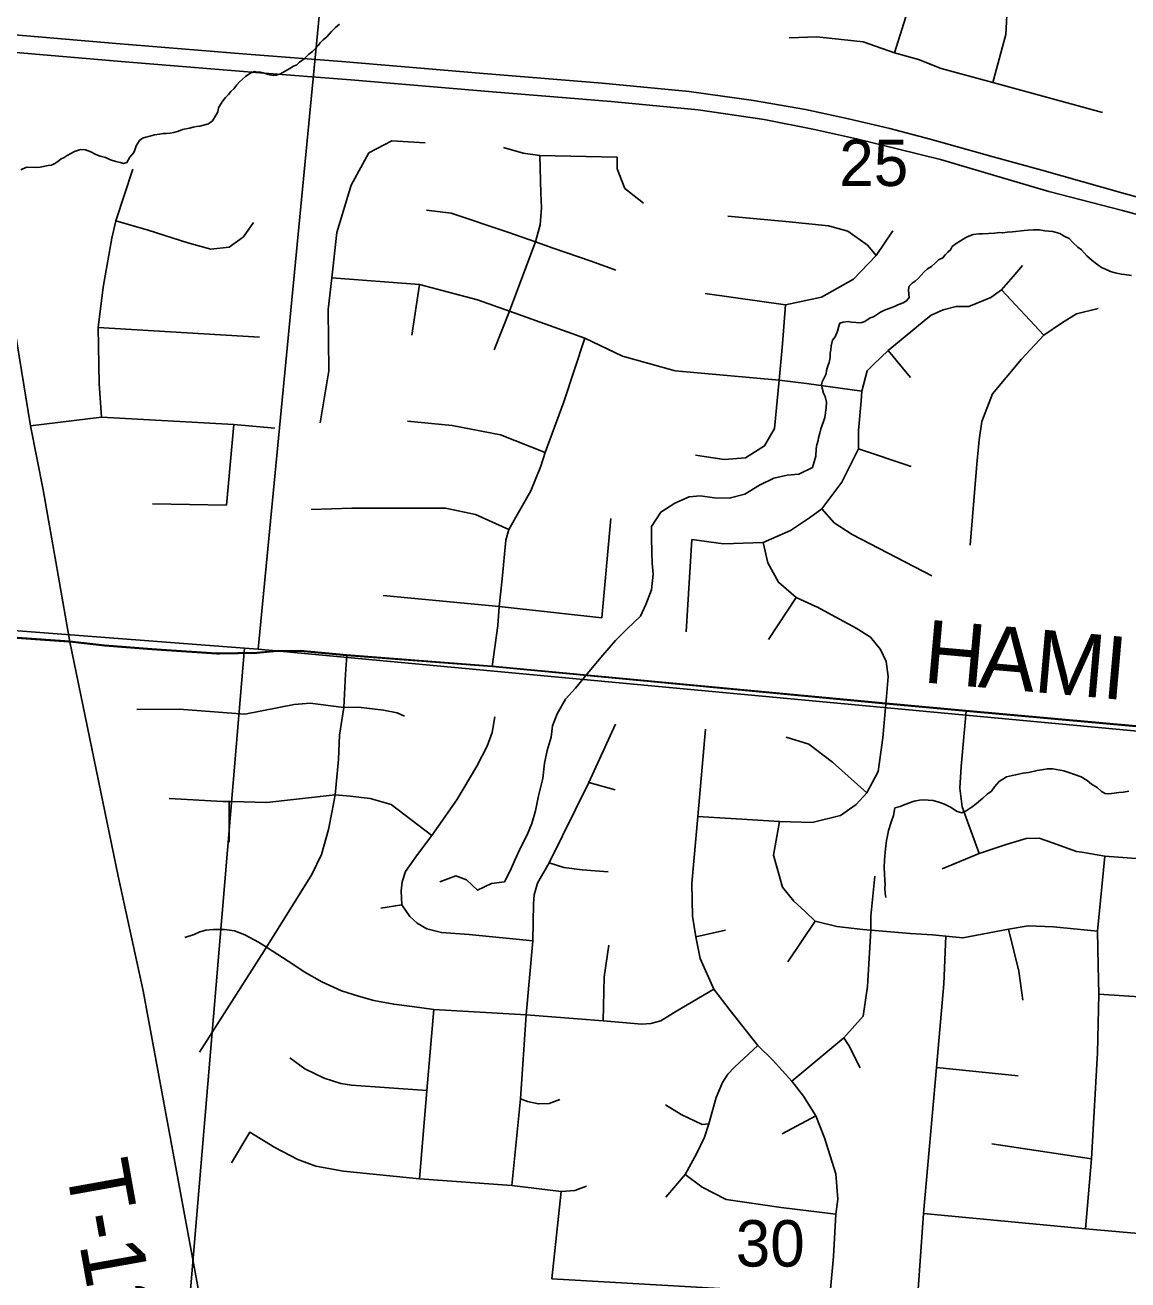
# Model space of a CAD drawing. Extents: x 0 to 34, y 0 to 22.
# Drawn here: x 6.638 to 7.633, y 19.591 to 20.723 of the extents above; entities that cross this region are included whole.
import ezdxf

# ---------------------------------------------------------------- set-up
doc = ezdxf.new("R2010")
doc.units = 0
for name, color, linetype in [('Default', 7, 'Continuous'), ('GM_X_Minor_River', 7, 'Continuous'), ('GM_X_Section', 7, 'Continuous'), ('GM_X_Section_Text', 7, 'Continuous'), ('GM_X_State_Route', 7, 'Continuous'), ('GM_X_Township_Road', 7, 'Continuous'), ('GM_X_Township_Road_Text', 7, 'Continuous')]:
    doc.layers.add(name, color=color, linetype=linetype)

msp = doc.modelspace()

# ---------------------------------------------------------------- linework, layer by layer
at = {"layer": 'Default'}
for points in [[(6.92, 20.9), (5.8864, 20.9), (5.8307, 20.238), (6.8362, 20.1611), (6.8487, 20.1601)], [(7.9386, 20.9), (6.92, 20.9), (6.8487, 20.1601), (7.855, 20.0664)]]:
    msp.add_lwpolyline(points, close=True, dxfattribs=at)
at = {"layer": 'GM_X_Minor_River'}
for points in [[(6.9221, 20.7242), (6.9183, 20.7212), (6.9148, 20.7175), (6.9105, 20.7126), (6.9074, 20.71), (6.9047, 20.7074), (6.9028, 20.7048), (6.9004, 20.7022), (6.8977, 20.6996), (6.8943, 20.697), (6.89, 20.6929), (6.8858, 20.6899), (6.8834, 20.6873), (6.8804, 20.6863), (6.8765, 20.6837), (6.8688, 20.6793), (6.865, 20.6782), (6.8624, 20.6779), (6.8593, 20.6783), (6.8533, 20.6803), (6.8506, 20.6808), (6.848, 20.6808), (6.8453, 20.6813), (6.8419, 20.6802), (6.8373, 20.6769), (6.8319, 20.672), (6.8295, 20.6694), (6.8268, 20.6657), (6.8241, 20.6635), (6.8218, 20.6608), (6.8191, 20.6579), (6.8167, 20.6549), (6.8148, 20.6515), (6.8128, 20.6485), (6.8124, 20.6451), (6.8108, 20.6424), (6.8073, 20.6368), (6.8038, 20.6342), (6.7961, 20.6321), (6.7931, 20.6318), (6.7901, 20.6311), (6.7866, 20.6304), (6.7805, 20.629), (6.7767, 20.6276), (6.7725, 20.6265), (6.7694, 20.6258), (6.766, 20.6255), (6.763, 20.6256), (6.7596, 20.6249), (6.755, 20.6242), (6.7508, 20.6231), (6.7473, 20.6221), (6.7443, 20.6214), (6.7416, 20.6191), (6.7385, 20.6143), (6.7376, 20.6112), (6.7364, 20.6082), (6.7329, 20.6041), (6.7302, 20.5992), (6.7271, 20.5985), (6.7241, 20.5994), (6.7203, 20.6002), (6.7154, 20.6018), (6.7109, 20.6038), (6.706, 20.605), (6.7022, 20.6066), (6.6977, 20.609), (6.6928, 20.6106), (6.6883, 20.6111), (6.6829, 20.6093), (6.6764, 20.6056), (6.6737, 20.6038), (6.671, 20.6027), (6.6679, 20.6001), (6.6652, 20.5983), (6.6622, 20.5968), (6.6591, 20.5965)], [(6.6591, 20.5965), (6.6519, 20.5951), (6.6485, 20.5948), (6.6397, 20.595), (6.6344, 20.5928)], [(7.6366, 20.4973), (7.6301, 20.4982), (7.6275, 20.4986), (7.6218, 20.4999), (7.6177, 20.5011), (7.6131, 20.5031), (7.6101, 20.5043), (7.6075, 20.5062), (7.6049, 20.5078), (7.6011, 20.5109), (7.5963, 20.5152), (7.5915, 20.5206), (7.5881, 20.523), (7.584, 20.5269), (7.5803, 20.5307), (7.5757, 20.5327), (7.572, 20.5351), (7.5656, 20.5371), (7.5584, 20.5376), (7.5535, 20.5385), (7.5481, 20.5386), (7.5432, 20.5383), (7.5398, 20.538), (7.5291, 20.5367), (7.5245, 20.5364), (7.5204, 20.5357), (7.5177, 20.5362), (7.5128, 20.5355), (7.5021, 20.535), (7.4987, 20.535), (7.4937, 20.5344), (7.4899, 20.5329), (7.4872, 20.5315), (7.4822, 20.5285), (7.4784, 20.5263), (7.4749, 20.5234), (7.4733, 20.5204), (7.4707, 20.5185), (7.4683, 20.5159), (7.4664, 20.5133), (7.4625, 20.5115), (7.4598, 20.5089), (7.456, 20.5055), (7.4525, 20.5033), (7.4494, 20.5007), (7.4467, 20.4977), (7.444, 20.4947), (7.4413, 20.4921), (7.4386, 20.4903), (7.4359, 20.4877), (7.4354, 20.4846), (7.4357, 20.4801), (7.436, 20.4774), (7.4337, 20.4744), (7.4306, 20.4726), (7.4257, 20.4708), (7.4226, 20.4693), (7.4195, 20.4682), (7.4138, 20.4661), (7.41, 20.4643), (7.4073, 20.4624), (7.4038, 20.4602), (7.4008, 20.4591), (7.3961, 20.4558), (7.3923, 20.4547), (7.384, 20.4553), (7.3809, 20.4557), (7.3764, 20.4551), (7.3733, 20.4544), (7.3725, 20.4517), (7.3713, 20.4472), (7.3693, 20.4419), (7.3669, 20.4389), (7.3657, 20.434)], [(7.3657, 20.434), (7.3652, 20.4302), (7.3648, 20.4272), (7.3647, 20.4234), (7.3639, 20.4188), (7.3627, 20.4158), (7.3615, 20.4117), (7.361, 20.4086), (7.3595, 20.4056), (7.3575, 20.4015), (7.357, 20.3988), (7.3574, 20.3958), (7.3588, 20.3912), (7.3602, 20.3881), (7.3613, 20.3832), (7.3612, 20.3779), (7.3599, 20.3691), (7.3587, 20.3657), (7.3563, 20.359), (7.3554, 20.3552), (7.3542, 20.351), (7.3538, 20.3484), (7.3526, 20.3446), (7.3521, 20.3412)], [(7.3521, 20.3412), (7.3517, 20.3343), (7.3488, 20.3242), (7.3365, 20.318), (7.3259, 20.3171), (7.314, 20.3144), (7.3009, 20.3083), (7.2878, 20.2999), (7.2737, 20.2964), (7.2604, 20.2968), (7.2475, 20.2986), (7.2376, 20.2977), (7.2246, 20.292), (7.2118, 20.2839), (7.2035, 20.2708), (7.2036, 20.2606), (7.2037, 20.2476), (7.2042, 20.2377), (7.2051, 20.2278), (7.2036, 20.2138), (7.1983, 20.2006), (7.1935, 20.1901), (7.1814, 20.1786), (7.1709, 20.1679), (7.1596, 20.1549), (7.1486, 20.1415), (7.1349, 20.1251), (7.1259, 20.1151), (7.1184, 20.1019), (7.1143, 20.091), (7.1129, 20.0808), (7.1095, 20.0687), (7.107, 20.0574), (7.1055, 20.0434), (7.1017, 20.0279), (7.0987, 20.0143), (7.0954, 20.0029), (7.0913, 19.9928), (7.0853, 19.9808), (7.0801, 19.9699), (7.076, 19.9601), (7.0709, 19.9503), (7.059, 19.9487), (7.0464, 19.9426), (7.0367, 19.952), (7.0269, 19.9556), (7.0124, 19.9503)], [(7.6341, 20.0322), (7.6292, 20.0312), (7.625, 20.0309), (7.6208, 20.0303), (7.6162, 20.0297), (7.6128, 20.0298), (7.6094, 20.0318), (7.6057, 20.0353), (7.6005, 20.0385), (7.5964, 20.0417), (7.5912, 20.0449), (7.5799, 20.049), (7.5754, 20.0503), (7.5655, 20.0521), (7.5606, 20.0523), (7.5572, 20.0516), (7.5514, 20.0507), (7.5438, 20.049), (7.5388, 20.0484), (7.5319, 20.0467), (7.5239, 20.045), (7.5173, 20.0407), (7.513, 20.0359), (7.5102, 20.0322), (7.5063, 20.0292), (7.5024, 20.0256), (7.4966, 20.0208), (7.4927, 20.0179), (7.4873, 20.0142), (7.4834, 20.0125), (7.4793, 20.0137), (7.4733, 20.0177), (7.4677, 20.0202)], [(7.4677, 20.0202), (7.4628, 20.0222), (7.4575, 20.0235), (7.453, 20.024), (7.4495, 20.0241), (7.4454, 20.0239), (7.4404, 20.0229), (7.4346, 20.0208), (7.4277, 20.0183), (7.4231, 20.017), (7.4218, 20.0102), (7.4197, 20.0041), (7.4172, 19.9966), (7.4163, 19.9917), (7.4154, 19.9875), (7.4149, 19.9826), (7.4143, 19.9769), (7.4137, 19.9697), (7.4135, 19.9633), (7.4138, 19.9576), (7.414, 19.9515), (7.4142, 19.948), (7.4141, 19.9446), (7.4144, 19.9397), (7.415, 19.9362)]]:
    msp.add_lwpolyline(points, dxfattribs=at)
at = {"layer": 'GM_X_Section'}
for points in [[(5.8307, 20.238), (6.8362, 20.1611), (6.7522, 19.1603), (5.7435, 19.3869), (5.8084, 20.2412)], [(6.8362, 20.1611), (6.8487, 20.1601), (7.855, 20.0664), (7.8637, 20.0659), (7.7938, 19.1583), (6.7522, 19.1603)]]:
    msp.add_lwpolyline(points, close=True, dxfattribs=at)
at = {"layer": 'GM_X_State_Route'}
for points in [[(6.5479, 20.7215), (6.7205, 20.7068), (6.8383, 20.6971), (6.924, 20.6905), (7.0518, 20.6797), (7.1589, 20.671), (7.2374, 20.6633), (7.2954, 20.6552), (7.3424, 20.6471), (7.3813, 20.6386), (7.4186, 20.63), (7.4549, 20.6203), (7.5117, 20.6045), (7.5555, 20.5923), (7.6278, 20.5719), (7.6871, 20.5558)], [(6.5561, 20.7048), (6.7287, 20.6902), (6.8465, 20.6805), (6.9322, 20.6739), (7.06, 20.6631), (7.1671, 20.6543), (7.2456, 20.6467), (7.3051, 20.6381), (7.3505, 20.629), (7.3885, 20.6208), (7.4642, 20.6019), (7.5203, 20.5856), (7.5619, 20.5732), (7.6283, 20.5559)], [(7.6283, 20.5559), (7.6361, 20.5538), (7.6945, 20.538), (7.7505, 20.5224), (7.8012, 20.5086), (7.8343, 20.4986), (7.8682, 20.4894)]]:
    msp.add_lwpolyline(points, dxfattribs=at)
at = {"layer": 'GM_X_Township_Road'}
for p, q in [((6.9943, 20.4891), (6.9873, 20.4436)), ((7.5574, 20.4434), (7.5192, 20.4844)), ((6.7044, 20.4503), (6.8499, 20.4416)), ((7.4171, 20.4297), (7.4373, 20.4053)), ((7.3902, 20.3408), (7.4379, 20.325)), ((7.3091, 20.1689), (7.334, 20.2069)), ((7.1469, 20.0398), (7.1707, 20.0333)), ((6.8224, 19.986), (6.8224, 20.0227)), ((6.9594, 19.9266), (6.9783, 19.9295)), ((7.2436, 19.9006), (7.2703, 19.9067)), ((7.3512, 19.9149), (7.3264, 19.8781)), ((7.4607, 19.7828), (7.5343, 19.7753)), ((7.3519, 19.7392), (7.3214, 19.7228)), ((7.6006, 19.7003), (7.5104, 19.7138)), ((7.1137, 19.5921), (7.1219, 19.6708)), ((7.1137, 19.5921), (7.265, 19.5834))]:
    msp.add_line(p, q, dxfattribs=at)
for points in [[(6.4945, 20.1803), (6.6784, 20.1674), (6.71, 20.1637), (6.7526, 20.1604), (6.7658, 20.1595), (6.8112, 20.1567), (6.8137, 20.1565), (6.8473, 20.1572), (6.8656, 20.1588), (6.8864, 20.1589), (6.9284, 20.155), (7.0596, 20.1449), (7.4148, 20.1115), (7.4871, 20.1047), (7.7604, 20.0801), (7.7765, 20.0797), (7.8238, 20.073), (7.9584, 20.0596), (8.6673, 19.9886), (8.7085, 19.9845), (8.8165, 19.9737), (8.9, 19.9667), (8.9, 20.9), (3.8479, 20.9)], [(7.4227, 20.6983), (7.4415, 20.7578), (7.4485, 20.7764), (7.4538, 20.7877), (7.4598, 20.8021), (7.4635, 20.8167), (7.4641, 20.8314)], [(7.5114, 20.6715), (7.5231, 20.7148), (7.5248, 20.7438), (7.5587, 20.7528)], [(7.3276, 20.7118), (7.3527, 20.7128), (7.3945, 20.7081), (7.4227, 20.6983), (7.4445, 20.6921), (7.4648, 20.6841), (7.5114, 20.6715), (7.6104, 20.6445)], [(6.6786, 20.1669), (6.6661, 20.2389), (6.6547, 20.3041), (6.6433, 20.3617), (6.6228, 20.4875), (6.6064, 20.5918), (6.5991, 20.6144), (6.591, 20.632)], [(6.9045, 20.3644), (6.9124, 20.4114), (6.9119, 20.4667), (6.9152, 20.4953), (6.9195, 20.536), (6.9326, 20.5789), (6.9486, 20.608), (6.9693, 20.6188), (6.9994, 20.6172)], [(7.0701, 20.6129), (7.0876, 20.6076), (7.1028, 20.6057), (7.1725, 20.6041), (7.1725, 20.5936), (7.1793, 20.5759), (7.1964, 20.5625)], [(7.0615, 20.4303), (7.0753, 20.4652), (7.0884, 20.4997), (7.0988, 20.5276), (7.1031, 20.5432), (7.1044, 20.5583), (7.1038, 20.5717), (7.1028, 20.6057)], [(6.7074, 20.3695), (6.7052, 20.3998), (6.7044, 20.4503), (6.7089, 20.4867), (6.7165, 20.5309), (6.7202, 20.5468), (6.7355, 20.5934)], [(7.0005, 20.5562), (7.0229, 20.5537), (7.074, 20.5364), (7.0988, 20.5276), (7.1147, 20.5219), (7.1492, 20.5103), (7.1713, 20.5023)], [(7.2723, 20.551), (7.3247, 20.5462), (7.3632, 20.5421), (7.3807, 20.5372), (7.3984, 20.5247), (7.4062, 20.5154)], [(6.7202, 20.5468), (6.7493, 20.5382), (6.7852, 20.5268), (6.8059, 20.5211), (6.8224, 20.5228), (6.8354, 20.5321), (6.8443, 20.5452)], [(7.252, 20.4811), (7.3245, 20.4709), (7.3569, 20.4779), (7.3858, 20.494), (7.4062, 20.5154), (7.4211, 20.5377)], [(7.2349, 20.1759), (7.2399, 20.259), (7.2686, 20.2552), (7.3043, 20.2563), (7.3288, 20.2672), (7.3461, 20.2788), (7.3572, 20.2869), (7.3751, 20.3108), (7.3902, 20.3408), (7.3902, 20.3574), (7.3927, 20.3843), (7.3932, 20.3929), (7.398, 20.4113), (7.4037, 20.4169), (7.4171, 20.4297), (7.4496, 20.4564), (7.4558, 20.4616), (7.4665, 20.4664), (7.4785, 20.4693), (7.4897, 20.4693), (7.5097, 20.4774), (7.5192, 20.4844), (7.5297, 20.4963), (7.5381, 20.5065)], [(6.9152, 20.4953), (6.9943, 20.4891), (7.0466, 20.4754), (7.0753, 20.4652), (7.1434, 20.4408), (7.1774, 20.4247), (7.2248, 20.4113), (7.3186, 20.4029), (7.3434, 20.4), (7.3932, 20.3929)], [(7.2433, 20.3353), (7.269, 20.3312), (7.2883, 20.3327), (7.3055, 20.3436), (7.3145, 20.3594), (7.3186, 20.4029), (7.3218, 20.4356), (7.3245, 20.4709)], [(7.4911, 20.2541), (7.4971, 20.327), (7.4992, 20.3491), (7.5016, 20.3656), (7.5111, 20.3905), (7.5374, 20.422), (7.5574, 20.4434), (7.5735, 20.4543), (7.5868, 20.4627), (7.6064, 20.4676)], [(7.0599, 20.1444), (7.0649, 20.1815), (7.066, 20.1986), (7.0689, 20.2237), (7.072, 20.2586), (7.0748, 20.2682), (7.0947, 20.3031), (7.1037, 20.3252), (7.1076, 20.3376), (7.1244, 20.3833), (7.1434, 20.4408)], [(6.6433, 20.3617), (6.7074, 20.3695), (6.8267, 20.3628), (6.8636, 20.3595)], [(6.7532, 20.2913), (6.82, 20.2902), (6.8267, 20.3628)], [(7.1076, 20.3376), (7.0672, 20.3537), (7.0236, 20.362), (6.9833, 20.3659)], [(5.1625, 20.2909), (5.3045, 20.2803), (5.4879, 20.2628), (5.632, 20.2501), (5.6711, 20.2466), (5.8283, 20.2358), (5.9419, 20.2248), (5.9874, 20.2213), (6.1326, 20.2085), (6.1948, 20.2048), (6.3755, 20.1881), (6.4947, 20.1797), (6.6776, 20.1669)], [(7.0748, 20.2682), (7.0448, 20.2818), (7.0176, 20.2873), (6.933, 20.2874), (6.8964, 20.2861)], [(7.3572, 20.2869), (7.3684, 20.2741), (7.3846, 20.2636), (7.4563, 20.2265)], [(7.1669, 20.278), (7.1586, 20.1885), (7.066, 20.1986), (6.9614, 20.2085)], [(7.3519, 20.1987), (7.334, 20.2069), (7.318, 20.2206), (7.3086, 20.2382), (7.3043, 20.2563)], [(7.4152, 20.1139), (7.417, 20.1355), (7.4153, 20.1492), (7.41, 20.1598), (7.401, 20.1709), (7.388, 20.1792), (7.3697, 20.189), (7.3527, 20.1983), (7.3519, 20.1987)], [(8.9, 14.8595), (8.9, 19.9667), (8.8165, 19.9737), (8.7085, 19.9845), (8.6673, 19.9886), (7.9584, 20.0596), (7.8238, 20.073), (7.7765, 20.0797), (7.7604, 20.0801), (7.4871, 20.1047), (7.4148, 20.1115), (7.0596, 20.1449), (6.9284, 20.155), (6.8864, 20.1589), (6.8656, 20.1588), (6.8473, 20.1572), (6.8137, 20.1565), (6.8112, 20.1567), (6.7658, 20.1595), (6.7526, 20.1604), (6.71, 20.1637), (6.6784, 20.1674), (6.4945, 20.1803)], [(6.6776, 20.1669), (6.6786, 20.1669), (6.7103, 20.1631), (6.7528, 20.1599), (6.766, 20.159), (6.8114, 20.1561), (6.8139, 20.156), (6.8475, 20.1567), (6.8658, 20.1583), (6.8867, 20.1584), (6.9287, 20.1545), (7.0599, 20.1444), (7.415, 20.111), (7.4873, 20.1042), (7.7606, 20.0795), (7.7767, 20.0792), (7.8122, 20.071), (7.8722, 20.0568), (7.9457, 20.0501), (7.9615, 20.0491)], [(6.8734, 19.1523), (6.8171, 19.4645), (6.8086, 19.507), (6.7449, 19.8518), (6.7224, 19.9555), (6.6786, 20.1669)], [(6.7956, 19.7966), (6.8562, 19.8912), (6.897, 19.957), (6.9058, 19.975), (6.912, 19.9974), (6.9155, 20.0142), (6.918, 20.0288), (6.9211, 20.0606), (6.9221, 20.0825), (6.9259, 20.1074), (6.9275, 20.1376), (6.9287, 20.1545)], [(6.7392, 20.1056), (6.7773, 20.1061), (6.8365, 20.1014), (6.8811, 20.1102), (6.8956, 20.1115), (6.9259, 20.1074), (6.9392, 20.1077), (6.9616, 20.1052), (6.974, 20.1028), (6.9808, 20.0996)], [(7.2453, 20.0091), (7.2898, 20.0066), (7.3191, 20.0048), (7.3483, 20.0039), (7.3739, 20.0101), (7.3882, 20.0199), (7.3979, 20.0306), (7.4081, 20.0498), (7.4121, 20.0803), (7.415, 20.111), (7.4152, 20.1139)], [(7.0965, 19.8969), (7.0389, 19.9026), (7.014, 19.9045), (7.0009, 19.9078), (6.9922, 19.9128), (6.9856, 19.9191), (6.9783, 19.9295), (6.9777, 19.9421), (6.9786, 19.9502), (6.9816, 19.9596), (6.9924, 19.9748), (7.0054, 19.9922), (7.028, 20.0242), (7.0458, 20.0546), (7.0551, 20.0726), (7.0599, 20.0851), (7.0622, 20.0992)], [(7.4991, 19.9757), (7.4838, 20.0179), (7.4817, 20.0347), (7.4829, 20.0544), (7.4873, 20.1042)], [(7.0776, 19.6763), (7.0854, 19.7543), (7.0905, 19.8301), (7.0965, 19.8969), (7.0969, 19.9303), (7.0977, 19.9386), (7.1008, 19.949), (7.1111, 19.9675), (7.1469, 20.0398), (7.171, 20.0925)], [(7.3612, 19.5378), (7.3625, 19.5523), (7.3643, 19.5761), (7.3678, 19.6123), (7.3699, 19.6503), (7.3717, 19.6639), (7.3697, 19.6867), (7.3597, 19.7193), (7.3519, 19.7392), (7.3405, 19.7568), (7.3302, 19.7704), (7.3128, 19.7897), (7.2993, 19.8025), (7.2746, 19.8341), (7.2597, 19.8535), (7.2475, 19.8811), (7.2436, 19.9006), (7.2404, 19.9192), (7.2398, 19.9486), (7.2453, 20.0091), (7.2521, 20.088)], [(7.3979, 20.0306), (7.3668, 20.0582), (7.3454, 20.0744), (7.3251, 20.0809)], [(6.7684, 20.0253), (6.8169, 20.0227), (6.8224, 20.0227), (6.8251, 20.0228), (6.8565, 20.0219), (6.918, 20.0288), (6.9316, 20.0276), (6.9498, 20.0253), (6.9686, 20.0199), (7.0054, 19.9922)], [(7.3191, 20.0048), (7.3136, 19.9744), (7.3216, 19.9455), (7.3318, 19.9328), (7.342, 19.9234), (7.3512, 19.9149), (7.3708, 19.9099), (7.3941, 19.9073), (7.4013, 19.9066), (7.4369, 19.9036)], [(7.5916, 19.9769), (7.5869, 19.9777), (7.5654, 19.9854), (7.5533, 19.9896), (7.5415, 19.9893), (7.5236, 19.984), (7.4991, 19.9757), (7.4658, 19.9619)], [(7.747, 19.905), (7.7355, 19.9251), (7.7151, 19.9462), (7.7001, 19.9601), (7.6898, 19.9666), (7.6753, 19.9691), (7.6527, 19.9704), (7.6125, 19.9735), (7.5916, 19.9769)], [(7.6065, 19.8748), (7.606, 19.9056), (7.6125, 19.9735)], [(7.1111, 19.9675), (7.1244, 19.9631), (7.141, 19.9611), (7.1644, 19.9592)], [(7.3302, 19.7704), (7.3769, 19.8095), (7.3946, 19.8289), (7.3983, 19.8558), (7.4013, 19.9066), (7.4013, 19.9193), (7.4051, 19.9553)], [(6.7826, 19.8999), (6.7908, 19.9028), (6.7961, 19.905), (6.8014, 19.9066), (6.8082, 19.9073), (6.8184, 19.9072), (6.8273, 19.9059), (6.8367, 19.9024), (6.8488, 19.8959), (6.8562, 19.8912), (6.8807, 19.8753), (6.8902, 19.8691), (6.9062, 19.8599), (6.9239, 19.852), (6.9392, 19.8472), (6.953, 19.8431), (6.9709, 19.8398), (6.9877, 19.8379), (7.0071, 19.8349), (7.0905, 19.8301), (7.1598, 19.8248), (7.1948, 19.8218), (7.2029, 19.8223), (7.212, 19.8248), (7.2256, 19.8333), (7.2597, 19.8535)], [(7.4369, 19.9036), (7.457, 19.9025), (7.469, 19.9012), (7.4845, 19.8996), (7.5257, 19.9075), (7.5433, 19.9105), (7.5661, 19.9097), (7.606, 19.9056)], [(7.5384, 19.8436), (7.5349, 19.8697), (7.5257, 19.9075)], [(7.4116, 19.1543), (7.4279, 19.3499), (7.4299, 19.3814), (7.431, 19.423), (7.4413, 19.5439), (7.449, 19.6509), (7.4607, 19.7828), (7.4673, 19.8582), (7.469, 19.9012)], [(7.1598, 19.8248), (7.1609, 19.8646), (7.165, 19.893)], [(7.6058, 19.7957), (7.607, 19.8489), (7.6065, 19.8748)], [(7.607, 19.8489), (7.6712, 19.8448), (7.749, 19.8386), (7.7791, 19.8371)], [(6.9942, 19.6823), (7.0008, 19.7621), (7.0071, 19.8349)], [(7.3769, 19.8095), (7.3815, 19.8027), (7.3917, 19.7824)], [(6.8773, 19.7914), (6.8906, 19.7816), (6.9081, 19.773), (6.9232, 19.7683), (6.9328, 19.7667), (7.0008, 19.7621)], [(7.2165, 19.6657), (7.234, 19.6861), (7.2444, 19.7055), (7.2514, 19.7198), (7.2553, 19.732), (7.2617, 19.7556), (7.2676, 19.7692), (7.2723, 19.7766), (7.2783, 19.7829), (7.2993, 19.8025)], [(7.595, 19.6372), (7.6006, 19.7003), (7.6057, 19.7908), (7.6058, 19.7957)], [(7.0854, 19.7543), (7.0917, 19.7519), (7.1015, 19.7498), (7.1112, 19.7501), (7.1207, 19.7538)], [(7.216, 19.7491), (7.2302, 19.7404), (7.2492, 19.7313), (7.2553, 19.732)], [(6.8245, 19.6967), (6.841, 19.7243), (6.8638, 19.7106), (6.8844, 19.6997), (6.9006, 19.6938), (6.9257, 19.6891), (6.9942, 19.6823), (7.0776, 19.6763), (7.1219, 19.6708), (7.1343, 19.6717), (7.1448, 19.6756)], [(7.234, 19.6861), (7.2491, 19.6748), (7.2709, 19.6636), (7.3205, 19.6565), (7.3699, 19.6503)], [(7.449, 19.6509), (7.595, 19.6372), (7.6735, 19.6301), (7.6875, 19.6297), (7.7497, 19.637), (7.7702, 19.639), (7.7938, 19.6421), (7.8178, 19.6463), (7.8426, 19.6571), (7.8558, 19.6642)]]:
    msp.add_lwpolyline(points, dxfattribs=at)

# ---------------------------------------------------------------- texts
at = {"layer": 'GM_X_Section_Text'}
for s, p in [('25', (7.3729, 20.5781)), ('30', (7.2795, 19.6031))]:
    msp.add_text(s, height=0.04186, rotation=0, dxfattribs=at).set_placement(p)
at = {"layer": 'GM_X_Township_Road_Text'}
for s, height, rotation, p in [('H', 0.0568, 354.9611, (7.4477, 20.1303)), ('A', 0.0568, 354.962, (7.4975, 20.126)), ('M', 0.0568, 354.9619, (7.5474, 20.1216)), ('I', 0.0568, 354.9586, (7.6088, 20.1161)), ('T-131', 0.05682, 280.2043, (6.6746, 19.6939))]:
    msp.add_text(s, height=height, rotation=rotation, dxfattribs=at).set_placement(p)

doc.saveas('drawing.dxf')
